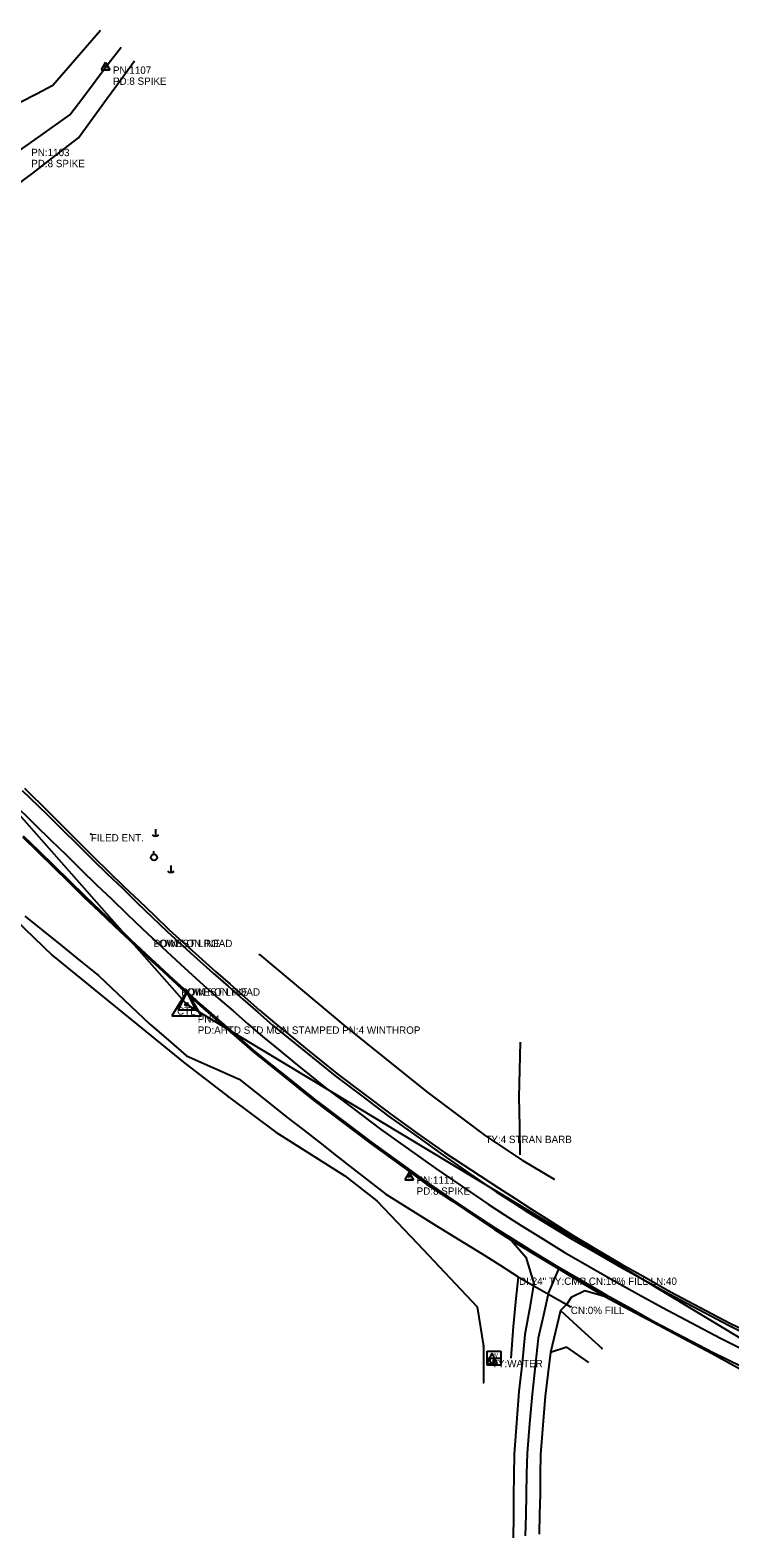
# Model space of a CAD drawing. Extents: x 592653 to 596268, y 1744647 to 1746025.
# Drawn here: x 594468 to 594943, y 1744801 to 1745824 of the extents above; entities that cross this region are included whole.
import ezdxf

# ---------------------------------------------------------------- set-up
doc = ezdxf.new("R2010")
doc.units = 0
for name, color, linetype in [('Default', 7, 'Continuous'), ('S_CAL_CORNER', 7, 'Continuous'), ('S_DITCHLINE', 7, 'Continuous'), ('S_DRG_PT_SYM', 7, 'Continuous'), ('S_DRIVEWAY', 7, 'Continuous'), ('S_EDGE_PAVEMENT', 7, 'Continuous'), ('S_ELECTRIC_UTILITIES_ANNOT', 7, 'Continuous'), ('S_FENCE', 7, 'Continuous'), ('S_FENCE_ANNOT', 7, 'Continuous'), ('S_MSC_PT_SYM', 7, 'Continuous'), ('S_PAVEMENT_CROWN', 7, 'Continuous'), ('S_PRIMARY_CTL', 7, 'Continuous'), ('S_PRIMARY_CTL_ANNOT', 7, 'Continuous'), ('S_SECONDARY_CTL', 7, 'Continuous'), ('S_SECONDARY_CTL_ANNOT', 7, 'Continuous'), ('S_SHOULDER', 7, 'Continuous'), ('S_SIDE_DRAIN', 7, 'Continuous'), ('S_SIDE_DRAIN_ANNOT', 7, 'Continuous'), ('S_STREAM', 7, 'Continuous'), ('S_SURVEY_TEXT_ANNOT', 7, 'Continuous'), ('S_UTILITY_POLE', 7, 'Continuous'), ('S_UTILITY_POLE_ANNOT', 7, 'Continuous'), ('S_UTL_PT_SYM', 7, 'Continuous'), ('S_WATER_UTILITIES', 7, 'Continuous')]:
    doc.layers.add(name, color=color, linetype=linetype)

msp = doc.modelspace()

# ---------------------------------------------------------------- linework, layer by layer
at = {"layer": 'Default'}
for p, q in [((594217.2, 1745566.8), (594574.3, 1745162.9)), ((594574.3, 1745162.9), (595099.2, 1744846.3))]:
    msp.add_line(p, q, dxfattribs=at)
at = {"layer": 'S_CAL_CORNER'}
for p, q in [((594574.4, 1745170.9), (594568.5, 1745159.1)), ((594574.4, 1745170.9), (594580.2, 1745159.1)), ((594568.5, 1745159.1), (594580.2, 1745159.1))]:
    msp.add_line(p, q, dxfattribs=at)
at = {"layer": 'S_DITCHLINE'}
for points in [[(594464.3, 1745222.9), (594476.8, 1745212.8), (594489.4, 1745202.7), (594501.9, 1745192.5), (594514.5, 1745182.4), (594531.9, 1745165.9), (594549.3, 1745149.4), (594561.7, 1745138.7), (594574.1, 1745127.9), (594592, 1745120), (594609.9, 1745112), (594626.1, 1745099.2), (594642.3, 1745086.3), (594653.5, 1745077.6), (594664.8, 1745068.8), (594676.1, 1745060), (594687.3, 1745051.3), (594698.4, 1745042.6), (594709.4, 1745034), (594725.8, 1745023.8), (594742.2, 1745013.7), (594758.6, 1745003.5), (594775, 1744993.4), (594787.2, 1744985.7), (594799.3, 1744977.9), (594797.6, 1744961), (594796, 1744944.1), (594794.3, 1744922.6)], [(594800.7, 1745137.2), (594800.3, 1745118.5), (594799.9, 1745099.8), (594800.2, 1745080.2), (594800.5, 1745060.7)]]:
    msp.add_lwpolyline(points, dxfattribs=at)
at = {"layer": 'S_DRG_PT_SYM'}
for points in [[(594800, 1744977.4), (594800, 1744977.5), (594800, 1744977.4), (594800, 1744977.4), (594800, 1744977.4), (594800, 1744977.4), (594800, 1744977.4), (594800.1, 1744977.4)], [(594835.1, 1744957.6), (594835.1, 1744957.7), (594835.1, 1744957.6), (594835.1, 1744957.6), (594835.1, 1744957.6), (594835.1, 1744957.6), (594835.1, 1744957.6), (594835.2, 1744957.6)]]:
    msp.add_lwpolyline(points, dxfattribs=at)
at = {"layer": 'S_DRIVEWAY'}
for points in [[(594828, 1744955), (594842.2, 1744942.1), (594856.3, 1744929.1), (594855.5, 1744929)], [(594847.4, 1744919.6), (594832.3, 1744930.2), (594821.3, 1744926.6)]]:
    msp.add_lwpolyline(points, dxfattribs=at)
at = {"layer": 'S_EDGE_PAVEMENT'}
for points in [[(594462.6, 1745308.1), (594479.2, 1745292), (594489.5, 1745281.8), (594499.8, 1745271.7), (594510.1, 1745261.6), (594520.4, 1745251.4), (594530.6, 1745241.7), (594540.7, 1745231.9), (594550.9, 1745222.2), (594561.1, 1745212.4), (594576.7, 1745198.2), (594592.3, 1745184), (594602.4, 1745175.2), (594612.4, 1745166.4), (594622.5, 1745157.6), (594632.6, 1745148.8), (594643.2, 1745140.2), (594653.8, 1745131.6), (594664.4, 1745122.9), (594675, 1745114.3), (594693.2, 1745100.7), (594711.4, 1745087), (594729.9, 1745073.8), (594748.4, 1745060.5), (594766.4, 1745048.1), (594784.4, 1745035.7), (594795.5, 1745028.5), (594806.7, 1745021.3), (594821.1, 1745012.5), (594835.5, 1745003.6), (594852.3, 1744994.1), (594869.1, 1744984.5), (594885.6, 1744975.4), (594902, 1744966.3), (594922.1, 1744955.6), (594942.2, 1744945), (594961.6, 1744935.3)], [(594463.3, 1745277.4), (594473.8, 1745267.2), (594484.3, 1745257), (594494.7, 1745246.7), (594505.2, 1745236.5), (594515.5, 1745226.7), (594525.9, 1745216.9), (594536.2, 1745207), (594546.5, 1745197.2), (594555.9, 1745188.6), (594565.2, 1745180), (594574.5, 1745171.4), (594583.8, 1745162.7), (594601.6, 1745147.3), (594619.5, 1745131.9), (594629.9, 1745123.5), (594640.4, 1745115.1), (594650.8, 1745106.7), (594661.2, 1745098.3), (594680.6, 1745083.7), (594699.9, 1745069), (594718.8, 1745055.5), (594737.6, 1745042), (594755.2, 1745030), (594772.8, 1745018.1), (594784, 1745010.9), (594795.3, 1745003.8), (594811.2, 1744994), (594827.2, 1744984.2), (594843.2, 1744974.9), (594859.2, 1744965.6), (594875.6, 1744956.5), (594892, 1744947.3), (594911.9, 1744936.9), (594931.8, 1744926.5), (594951.2, 1744917)], [(594794.5, 1745002.7), (594804.5, 1744991.2), (594810.1, 1744973.3), (594807.1, 1744955.9), (594804, 1744938.6), (594802, 1744919.3), (594799.9, 1744900), (594798.2, 1744878.8), (594796.6, 1744857.5), (594796.4, 1744843.3), (594796.3, 1744829.1), (594796.1, 1744814.8), (594796, 1744800.6)], [(594858.7, 1744964.3), (594844.6, 1744968.3), (594835.4, 1744963.9), (594832.3, 1744959.3), (594828, 1744955), (594824.7, 1744940.8), (594821.3, 1744926.6), (594819.6, 1744911.8), (594817.8, 1744896.9), (594816.2, 1744877.1), (594814.6, 1744857.2), (594814.4, 1744843.7), (594814.2, 1744830.2), (594813.9, 1744816.7), (594813.7, 1744803.2)]]:
    msp.add_lwpolyline(points, dxfattribs=at)
at = {"layer": 'S_FENCE'}
for p, q in [((594338.5, 1745335.3), (594483.1, 1745196.1)), ((594483.1, 1745196.1), (594572.1, 1745123.7)), ((594623.8, 1745196.7), (594682.1, 1745147.8)), ((594682.1, 1745147.8), (594737.4, 1745103.5)), ((594572.1, 1745123.7), (594602.6, 1745100)), ((594602.6, 1745100), (594634.9, 1745076.1)), ((594737.4, 1745103.5), (594777.1, 1745073.7)), ((594634.9, 1745076.1), (594681.7, 1745046.5)), ((594777.1, 1745073.7), (594802.1, 1745057.1)), ((594802.1, 1745057.1), (594823.7, 1745044.2)), ((594681.7, 1745046.5), (594703.4, 1745029.5)), ((594703.4, 1745029.5), (594731.1, 1745000.5)), ((594731.1, 1745000.5), (594771.5, 1744957.4)), ((594771.5, 1744957.4), (594775.8, 1744930.7)), ((594775.8, 1744930.7), (594775.9, 1744905.9))]:
    msp.add_line(p, q, dxfattribs=at)
at = {"layer": 'S_MSC_PT_SYM'}
for points in [[(594509.2, 1745278.5), (594509.2, 1745278.6), (594509.2, 1745278.5), (594509.1, 1745278.5), (594509.2, 1745278.5), (594509.2, 1745278.5), (594509.2, 1745278.5), (594509.2, 1745278.5)], [(594551.8, 1745206.8), (594551.8, 1745206.9), (594551.8, 1745206.8), (594551.7, 1745206.8), (594551.8, 1745206.8), (594551.8, 1745206.8), (594551.8, 1745206.8), (594551.8, 1745206.8)], [(594483.1, 1745196.1), (594483.1, 1745196.2), (594483.1, 1745196.1), (594483, 1745196.1), (594483.1, 1745196.1), (594483.1, 1745196.1), (594483.1, 1745196.1), (594483.1, 1745196.1)], [(594623.8, 1745196.7), (594623.8, 1745196.7), (594623.8, 1745196.7), (594623.7, 1745196.7), (594623.8, 1745196.7), (594623.8, 1745196.6), (594623.8, 1745196.7), (594623.8, 1745196.7)], [(594570.6, 1745173.8), (594570.6, 1745173.8), (594570.6, 1745173.8), (594570.6, 1745173.8), (594570.6, 1745173.8), (594570.6, 1745173.7), (594570.6, 1745173.8), (594570.7, 1745173.8)], [(594682.1, 1745147.8), (594682.1, 1745147.9), (594682.1, 1745147.8), (594682, 1745147.8), (594682.1, 1745147.8), (594682.1, 1745147.8), (594682.1, 1745147.8), (594682.1, 1745147.8)], [(594572.1, 1745123.7), (594572.1, 1745123.7), (594572.1, 1745123.7), (594572, 1745123.7), (594572.1, 1745123.7), (594572.1, 1745123.6), (594572.1, 1745123.7), (594572.1, 1745123.7)], [(594602.6, 1745100), (594602.6, 1745100), (594602.6, 1745100), (594602.6, 1745100), (594602.6, 1745100), (594602.6, 1745099.9), (594602.6, 1745100), (594602.7, 1745100)], [(594737.4, 1745103.5), (594737.4, 1745103.5), (594737.4, 1745103.5), (594737.3, 1745103.5), (594737.4, 1745103.5), (594737.4, 1745103.4), (594737.4, 1745103.5), (594737.4, 1745103.5)], [(594634.9, 1745076.1), (594634.9, 1745076.1), (594634.9, 1745076.1), (594634.9, 1745076.1), (594634.9, 1745076.1), (594634.9, 1745076), (594634.9, 1745076.1), (594635, 1745076.1)], [(594777.1, 1745073.7), (594777.1, 1745073.8), (594777.1, 1745073.7), (594777.1, 1745073.7), (594777.1, 1745073.7), (594777.1, 1745073.7), (594777.1, 1745073.7), (594777.2, 1745073.7)], [(594802.1, 1745057.1), (594802.1, 1745057.1), (594802.1, 1745057.1), (594802.1, 1745057.1), (594802.1, 1745057.1), (594802.1, 1745057), (594802.1, 1745057.1), (594802.2, 1745057.1)], [(594681.7, 1745046.5), (594681.7, 1745046.5), (594681.7, 1745046.5), (594681.6, 1745046.5), (594681.7, 1745046.5), (594681.7, 1745046.4), (594681.7, 1745046.5), (594681.7, 1745046.5)], [(594823.7, 1745044.2), (594823.7, 1745044.3), (594823.7, 1745044.2), (594823.6, 1745044.2), (594823.7, 1745044.2), (594823.7, 1745044.2), (594823.7, 1745044.2), (594823.7, 1745044.2)], [(594703.4, 1745029.5), (594703.4, 1745029.6), (594703.4, 1745029.5), (594703.4, 1745029.5), (594703.4, 1745029.5), (594703.4, 1745029.5), (594703.4, 1745029.5), (594703.5, 1745029.5)], [(594731.1, 1745000.5), (594731.1, 1745000.6), (594731.1, 1745000.5), (594731, 1745000.5), (594731.1, 1745000.5), (594731.1, 1745000.5), (594731.1, 1745000.5), (594731.1, 1745000.5)], [(594771.5, 1744957.4), (594771.5, 1744957.5), (594771.5, 1744957.4), (594771.4, 1744957.4), (594771.5, 1744957.4), (594771.5, 1744957.4), (594771.5, 1744957.4), (594771.5, 1744957.4)], [(594775.8, 1744930.7), (594775.8, 1744930.8), (594775.8, 1744930.7), (594775.7, 1744930.7), (594775.8, 1744930.7), (594775.8, 1744930.7), (594775.8, 1744930.7), (594775.8, 1744930.7)], [(594775.9, 1744905.9), (594775.9, 1744906), (594775.9, 1744905.9), (594775.8, 1744905.9), (594775.9, 1744905.9), (594775.9, 1744905.9), (594775.9, 1744905.9), (594775.9, 1744905.9)]]:
    msp.add_lwpolyline(points, dxfattribs=at)
at = {"layer": 'S_PAVEMENT_CROWN'}
for points in [[(594455.1, 1745300.9), (594471.7, 1745284.6), (594482, 1745274.5), (594492.4, 1745264.4), (594502.7, 1745254.3), (594513.1, 1745244.1), (594523.4, 1745234.3), (594533.7, 1745224.4), (594544.1, 1745214.5), (594554.4, 1745204.6), (594570.1, 1745190.2), (594585.7, 1745175.9), (594595.7, 1745167.2), (594605.8, 1745158.4), (594615.8, 1745149.7), (594625.8, 1745141), (594636.4, 1745132.4), (594647.1, 1745123.7), (594657.7, 1745115.1), (594668.3, 1745106.4), (594687.1, 1745092.3), (594705.9, 1745078.2), (594724.6, 1745064.9), (594743.4, 1745051.5), (594761.1, 1745039.4), (594778.9, 1745027.3), (594790.1, 1745020), (594801.3, 1745012.7), (594816, 1745003.7), (594830.7, 1744994.7), (594847.6, 1744984.9), (594864.5, 1744975.1), (594880.9, 1744966), (594897.3, 1744957), (594917.1, 1744946.6), (594936.8, 1744936.2), (594956.3, 1744926.5)], [(594827.2, 1744984.2), (594820, 1744967.3), (594816.5, 1744951.8), (594812.9, 1744936.3), (594810.8, 1744917.2), (594808.8, 1744898.1), (594807.1, 1744878.2), (594805.4, 1744858.2), (594805.1, 1744844.2), (594804.8, 1744830.2), (594804.5, 1744816.1), (594804.2, 1744802.1)]]:
    msp.add_lwpolyline(points, dxfattribs=at)
at = {"layer": 'S_PRIMARY_CTL'}
for p, q in [((594574.3, 1745171.6), (594564.3, 1745155.1)), ((594574.3, 1745171.6), (594564.3, 1745155.1)), ((594574.3, 1745171.6), (594584.2, 1745155.1)), ((594574.3, 1745171.6), (594584.2, 1745155.1)), ((594564.3, 1745155.1), (594584.2, 1745155.1)), ((594564.3, 1745155.1), (594584.2, 1745155.1))]:
    msp.add_line(p, q, dxfattribs=at)
for radius in [1.04, 1.04, 0.609, 0.609, 0.344, 0.344]:
    msp.add_circle((594574.3, 1745162.9), radius, dxfattribs=at)
at = {"layer": 'S_SECONDARY_CTL'}
for p, q in [((594519.2, 1745802.4), (594516.2, 1745797.4)), ((594516.2, 1745797.4), (594522.2, 1745797.4)), ((594519.2, 1745802.4), (594522.2, 1745797.4)), ((594725.4, 1745048.7), (594722.4, 1745043.8)), ((594725.4, 1745048.7), (594728.4, 1745043.8)), ((594722.4, 1745043.8), (594728.4, 1745043.8))]:
    msp.add_line(p, q, dxfattribs=at)
for centre, radius in [((594519.2, 1745799.8), 0.311), ((594519.2, 1745799.8), 0.183), ((594519.2, 1745799.8), 0.103), ((594725.4, 1745046.1), 0.311), ((594725.4, 1745046.1), 0.183), ((594725.4, 1745046.1), 0.103)]:
    msp.add_circle(centre, radius, dxfattribs=at)
at = {"layer": 'S_SHOULDER'}
for points in [[(594464.2, 1745309.6), (594480.6, 1745293.3), (594490.8, 1745283.2), (594501.1, 1745273), (594511.3, 1745262.9), (594521.5, 1745252.8), (594531.7, 1745243), (594542, 1745233.2), (594552.2, 1745223.4), (594562.4, 1745213.6), (594578.1, 1745199.4), (594593.8, 1745185.3), (594603.8, 1745176.5), (594613.8, 1745167.8), (594623.8, 1745159), (594633.9, 1745150.3), (594644.5, 1745141.7), (594655, 1745133.1), (594665.6, 1745124.6), (594676.2, 1745116), (594694.5, 1745102.2), (594712.8, 1745088.3), (594731.1, 1745075.3), (594749.4, 1745062.3), (594767.7, 1745050.2), (594786, 1745038.2), (594797.3, 1745031.1), (594808.5, 1745023.9), (594822.5, 1745014.9), (594836.6, 1745005.9), (594853, 1744996.2), (594869.5, 1744986.5), (594886.2, 1744977.1), (594902.9, 1744967.7), (594923, 1744957.1), (594943.1, 1744946.4), (594962.3, 1744937.2)], [(594462.7, 1745276.7), (594473.2, 1745266.4), (594483.6, 1745256.2), (594494, 1745246), (594504.5, 1745235.7), (594514.8, 1745226), (594525.1, 1745216.2), (594535.5, 1745206.4), (594545.8, 1745196.6), (594555.3, 1745187.9), (594564.7, 1745179.3), (594574.1, 1745170.6), (594583.6, 1745161.9), (594601.2, 1745146.5), (594618.9, 1745131.1), (594629.4, 1745122.8), (594639.8, 1745114.4), (594650.2, 1745106), (594660.7, 1745097.7), (594680.1, 1745083), (594699.5, 1745068.3), (594718.3, 1745054.6), (594737.1, 1745040.9), (594754.7, 1745029.2), (594772.3, 1745017.5), (594783.4, 1745010.1), (594794.5, 1745002.7), (594810.6, 1744993.1), (594826.6, 1744983.5), (594842.6, 1744973.9), (594858.7, 1744964.3), (594875.1, 1744955.5), (594891.5, 1744946.8), (594911.3, 1744936.2), (594931, 1744925.7), (594950.3, 1744915.2)]]:
    msp.add_lwpolyline(points, dxfattribs=at)
at = {"layer": 'S_SIDE_DRAIN'}
msp.add_line((594800, 1744977.4), (594835.1, 1744957.6), dxfattribs=at)
at = {"layer": 'S_STREAM'}
for points in [[(594182.9, 1745623.6), (594195.7, 1745628.8), (594208.5, 1745633.9), (594221.3, 1745639.1), (594234, 1745644.2), (594256.2, 1745651.5), (594278.4, 1745658.7), (594291.6, 1745667.5), (594304.8, 1745676.3), (594318.3, 1745687.3), (594331.8, 1745698.2), (594345.4, 1745709.1), (594358.9, 1745720.1), (594378.9, 1745731), (594398.9, 1745742), (594418.9, 1745752.9), (594438.9, 1745763.9), (594450.1, 1745769.7), (594461.2, 1745775.5), (594472.3, 1745781.3), (594483.4, 1745787.1), (594499.6, 1745805.8), (594515.7, 1745824.5)], [(594201.9, 1745610.5), (594223.8, 1745619.3), (594245.7, 1745628), (594265.2, 1745636.8), (594284.6, 1745645.5), (594298.9, 1745653.1), (594313.2, 1745660.6), (594332.5, 1745671.2), (594351.8, 1745681.8), (594371.1, 1745692.4), (594390.4, 1745703), (594406.7, 1745712), (594422.9, 1745720.9), (594439.1, 1745729.9), (594455.4, 1745738.8), (594475.2, 1745752.9), (594495, 1745767), (594503.7, 1745778.5), (594512.3, 1745790), (594521, 1745801.5), (594529.7, 1745813)], [(594221.8, 1745585), (594240.5, 1745596.8), (594259.1, 1745608.7), (594271.5, 1745616.1), (594283.8, 1745623.5), (594305.4, 1745634), (594327.1, 1745644.5), (594345.3, 1745652.5), (594363.5, 1745660.4), (594381.7, 1745668.4), (594399.9, 1745676.3), (594417.4, 1745689.1), (594434.9, 1745701.8), (594452.3, 1745714.5), (594469.8, 1745727.3), (594485.3, 1745739.4), (594500.8, 1745751.4), (594510.3, 1745764.5), (594519.8, 1745777.5), (594529.3, 1745790.5), (594538.8, 1745803.6)]]:
    msp.add_lwpolyline(points, dxfattribs=at)
at = {"layer": 'S_UTILITY_POLE'}
for p, q in [((594553, 1745281.8), (594553, 1745277)), ((594552, 1745264.9), (594552, 1745267)), ((594563.5, 1745257.2), (594563.5, 1745252.5)), ((594781.5, 1744926), (594778, 1744918.9)), ((594781.5, 1744926), (594785, 1744918.9)), ((594778, 1744918.9), (594785, 1744918.9)), ((594780.3, 1744920.2), (594780.3, 1744922.6)), ((594781, 1744919.5), (594780.3, 1744920.2)), ((594782.2, 1744919.5), (594781, 1744919.5)), ((594782.7, 1744920.2), (594782.2, 1744919.5)), ((594782.7, 1744922.6), (594782.7, 1744920.2))]:
    msp.add_line(p, q, dxfattribs=at)
msp.add_circle((594552.1, 1745262.7), 2.13, dxfattribs=at)
for centre in [(594553.1, 1745280.5), (594563.5, 1745255.9)]:
    msp.add_arc(centre, 3.41, 226.3972, 313.6028, dxfattribs=at)
at = {"layer": 'S_UTL_PT_SYM'}
for points in [[(594551.8, 1745206.8), (594551.8, 1745206.9), (594551.8, 1745206.8), (594551.7, 1745206.8), (594551.8, 1745206.8), (594551.8, 1745206.8), (594551.8, 1745206.8), (594551.8, 1745206.8)], [(594570.6, 1745173.8), (594570.6, 1745173.8), (594570.6, 1745173.8), (594570.6, 1745173.8), (594570.6, 1745173.8), (594570.6, 1745173.7), (594570.6, 1745173.8), (594570.7, 1745173.8)]]:
    msp.add_lwpolyline(points, dxfattribs=at)
at = {"layer": 'S_WATER_UTILITIES'}
for p, q in [((594778.2, 1744927.3), (594787.6, 1744927.3)), ((594778.2, 1744917.9), (594778.2, 1744927.3)), ((594787.6, 1744927.3), (594787.6, 1744917.9)), ((594778.2, 1744922.6), (594787.6, 1744922.6)), ((594787.6, 1744917.9), (594778.2, 1744917.9))]:
    msp.add_line(p, q, dxfattribs=at)

# ---------------------------------------------------------------- texts
at = {"layer": 'S_ELECTRIC_UTILITIES_ANNOT'}
for p in [(594551.8, 1745201.8), (594570.6, 1745168.8)]:
    msp.add_text('LOWEST LINE', height=5, dxfattribs=at).set_placement(p)
at = {"layer": 'S_FENCE_ANNOT'}
msp.add_text('TY:4 STRAN BARB', height=5, dxfattribs=at).set_placement((594777.1, 1745068.7))
at = {"layer": 'S_PRIMARY_CTL'}
msp.add_text('CTL', height=5, rotation=360, dxfattribs=at).set_placement((594567.7, 1745155.9))
msp.add_text('CTL', height=5, rotation=360, dxfattribs=at).set_placement((594567.7, 1745155.9))
at = {"layer": 'S_PRIMARY_CTL_ANNOT'}
for s, p in [('PN:4', (594581.8, 1745150.4)), ('PD:AHTD STD MON STAMPED PN:4 WINTHROP', (594581.8, 1745142.9))]:
    msp.add_text(s, height=5, dxfattribs=at).set_placement(p)
at = {"layer": 'S_SECONDARY_CTL'}
for p in [(594518, 1745797.8), (594724.2, 1745044.1)]:
    msp.add_text('TV', height=1.5, rotation=360, dxfattribs=at).set_placement(p)
at = {"layer": 'S_SECONDARY_CTL_ANNOT'}
for s, p in [('PN:1107', (594524.2, 1745794.8)), ('PD:8 SPIKE', (594524.2, 1745787.3)), ('PN:1103', (594468.7, 1745738.9)), ('PD:8 SPIKE', (594468.7, 1745731.4)), ('PN:1111', (594730.4, 1745041.1)), ('PD:8 SPIKE', (594730.4, 1745033.6))]:
    msp.add_text(s, height=5, dxfattribs=at).set_placement(p)
at = {"layer": 'S_SIDE_DRAIN_ANNOT'}
for s, p in [('DI:24" TY:CMP CN:10% FILL LN:40', (594800, 1744972.4)), ('CN:0% FILL', (594835.1, 1744952.6))]:
    msp.add_text(s, height=5, dxfattribs=at).set_placement(p)
at = {"layer": 'S_SURVEY_TEXT_ANNOT'}
for s, p in [('FILED ENT.', (594509.2, 1745273.5)), ('POINT ON ROAD', (594551.8, 1745201.8)), ('POINT ON ROAD', (594570.6, 1745168.8))]:
    msp.add_text(s, height=5, dxfattribs=at).set_placement(p)
at = {"layer": 'S_UTILITY_POLE_ANNOT'}
msp.add_text('TY:WATER', height=5, dxfattribs=at).set_placement((594781.5, 1744916.5))
at = {"layer": 'S_WATER_UTILITIES'}
for s, p in [('W', (594781.7, 1744923.2)), ('V', (594782, 1744919.1))]:
    msp.add_text(s, height=3, rotation=360, dxfattribs=at).set_placement(p)

doc.saveas('drawing.dxf')
